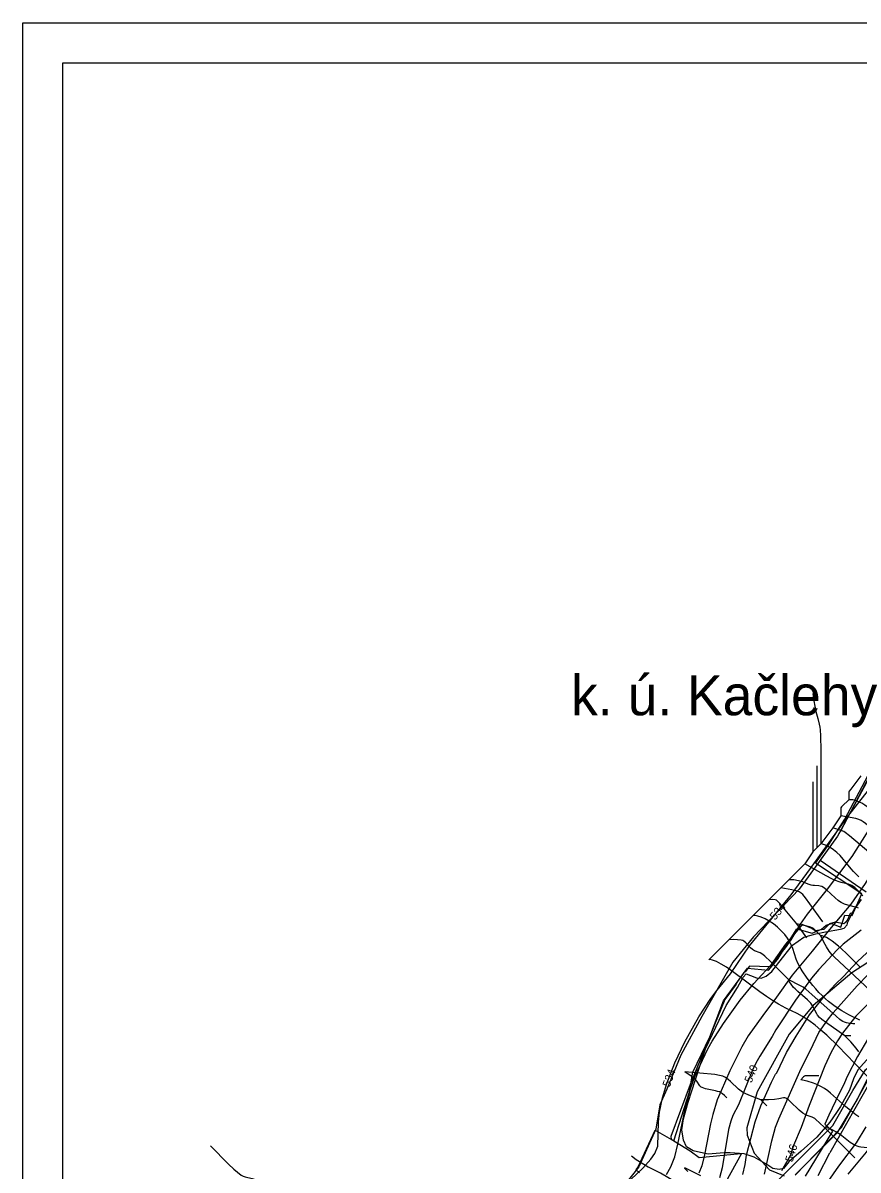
# Model space of a CAD drawing. Extents: x -709584 to -702006, y -1161789 to -1157496.
# Drawn here: x -709584 to -708540, y -1158930 to -1157496 of the extents above; entities that cross this region are included whole.
import ezdxf

# ---------------------------------------------------------------- set-up
doc = ezdxf.new("R2010")
doc.units = 0
for name, color, linetype in [('102_obvod PÚ', 7, 'Continuous'), ('103_hranice KÚ', 7, 'Continuous'), ('104_název KÚ', 7, 'Continuous'), ('110_silnice II. třídy a III. třídy', 7, 'Continuous'), ('120_vrstevnice hlavní', 7, 'Continuous'), ('121_vrstevnice hlavní_popis', 7, 'Continuous'), ('122_vrstevnice základní', 7, 'Continuous'), ('408_BPEJ_linie', 7, 'Continuous'), ('411_akumulovaný odtok', 7, 'Continuous'), ('419_LPIS PB', 7, 'Continuous'), ('501_vodní tok', 7, 'Continuous'), ('800_mřížka', 7, 'Continuous')]:
    doc.layers.add(name, color=color, linetype=linetype)

msp = doc.modelspace()

# ---------------------------------------------------------------- linework, layer by layer
at = {"layer": '102_obvod PÚ'}
for points in [[(-708813.3, -1158933.4), (-708817.7, -1158929.6), (-708815.4, -1158926.5), (-708793.7, -1158880.1), (-708770.5, -1158893.3), (-708750.8, -1158832), (-708746.8, -1158807.3), (-708725.5, -1158763.1), (-708708.5, -1158718.2), (-708678.4, -1158677.6), (-708652.2, -1158679.9), (-708641.1, -1158666.5), (-708617, -1158628.4), (-708597.6, -1158633.7), (-708586.1, -1158628.9), (-708580, -1158623.8), (-708573.6, -1158621.5), (-708561.7, -1158626.2), (-708556.8, -1158611.3), (-708547.7, -1158611.7), (-708535.6, -1158584.7), (-708593.5, -1158546.1), (-708576.9, -1158523.1), (-708562.5, -1158500.5), (-708557, -1158491.2), (-708524.4, -1158430.1)], [(-707921.8, -1158971), (-707999.1, -1158885.4), (-708014, -1158900), (-708117.7, -1158840.9), (-708144.9, -1158823.8), (-708143.2, -1158818), (-708120.7, -1158790.7), (-708182.3, -1158755), (-708195.8, -1158778.2), (-708236.7, -1158752.8), (-708244.6, -1158757.8), (-708255.9, -1158750.9), (-708298.9, -1158724), (-708301.6, -1158715.7), (-708309.8, -1158710.6), (-708354.7, -1158714.5), (-708370.1, -1158717.6), (-708390.1, -1158717.3), (-708405.6, -1158715.6), (-708506.3, -1158796.6), (-708529, -1158816.5), (-708541.9, -1158842.1), (-708567, -1158883.8), (-708618.5, -1158935.5)]]:
    msp.add_lwpolyline(points, dxfattribs=at)
at = {"layer": '103_hranice KÚ'}
msp.add_lwpolyline([(-708525.2, -1158435.6), (-708554.4, -1158491.4), (-708566, -1158512.4), (-708599.3, -1158558.9), (-708614.1, -1158578.7), (-708671.1, -1158638.5), (-708697, -1158669.9), (-708735.7, -1158737.7), (-708761.7, -1158786), (-708779.1, -1158828.5), (-708787.9, -1158848.4), (-708792.9, -1158878.8), (-708814.3, -1158925.7), (-708857.7, -1158980.1)], dxfattribs=at)
msp.add_lwpolyline([(-708525.2, -1158435.6), (-708554.4, -1158491.4), (-708566, -1158512.4), (-708599.3, -1158558.9), (-708614.1, -1158578.7), (-708671.1, -1158638.5), (-708697, -1158669.9), (-708735.7, -1158737.7), (-708761.7, -1158786), (-708779.1, -1158828.5), (-708787.9, -1158848.4), (-708792.9, -1158878.8), (-708814.3, -1158925.7), (-708857.7, -1158980.1)], dxfattribs=at)
at = {"layer": '110_silnice II. třídy a III. třídy'}
msp.add_lwpolyline([(-708704.4, -1159007.2), (-708617.3, -1158919.6), (-708571.8, -1158874.2), (-708546.8, -1158830.3), (-708531, -1158804.5), (-708476, -1158757.1), (-708390.8, -1158691.1), (-708373, -1158681.6), (-708289.6, -1158664.2), (-708263.7, -1158660.9), (-708218.7, -1158674.7), (-708130.2, -1158710.6), (-708061.3, -1158767.5), (-707984.1, -1158831.3), (-707891.2, -1158926), (-707846, -1158974.2)], dxfattribs=at)
at = {"layer": '120_vrstevnice hlavní'}
for points in [[(-708536.6, -1158629.9), (-708559.1, -1158647.7), (-708566.6, -1158654.4), (-708589.2, -1158679.1), (-708598.4, -1158690.1), (-708618.6, -1158717.3), (-708643.1, -1158754.7), (-708647.8, -1158763), (-708663.1, -1158787.4), (-708667.9, -1158796), (-708672.2, -1158805), (-708689.9, -1158848.4), (-708696.9, -1158861.7), (-708699.4, -1158868.7), (-708702.1, -1158879), (-708710.1, -1158927), (-708713.5, -1158939.6)], [(-708523.4, -1158816.8), (-708575.5, -1158908.3)], [(-708590.2, -1158936.7), (-708575.5, -1158908.3)]]:
    msp.add_lwpolyline(points, dxfattribs=at)
at = {"layer": '122_vrstevnice základní'}
for points in [[(-708422.3, -1158397.3), (-708431.3, -1158415.6), (-708438.3, -1158427), (-708472.2, -1158476), (-708487.1, -1158501.6), (-708497.5, -1158517.1), (-708531.5, -1158571.6), (-708549.4, -1158597.7), (-708575.8, -1158629.3), (-708597.5, -1158656.3), (-708622.8, -1158686.1), (-708642.1, -1158713.9), (-708659.5, -1158736.6), (-708677.8, -1158762.1), (-708685.6, -1158775.9), (-708700.4, -1158805.6), (-708711.6, -1158830.7), (-708716.2, -1158842.2), (-708721.9, -1158860.4), (-708724.8, -1158871.9), (-708732.2, -1158910.7), (-708735.5, -1158924.4), (-708739.1, -1158933.6)], [(-708839.8, -1158956), (-708809.1, -1158927.2), (-708799.5, -1158916.2), (-708794.4, -1158909), (-708790.5, -1158899.9), (-708789.9, -1158869.6), (-708788.5, -1158857.6), (-708784.6, -1158839.6), (-708779.1, -1158821.6), (-708769.4, -1158795.6), (-708756.6, -1158769.6), (-708739.4, -1158738.4), (-708724.2, -1158715.3), (-708716.5, -1158704.9), (-708699.9, -1158684.4), (-708676.1, -1158649.4), (-708623.8, -1158585.7), (-708599.6, -1158553.1), (-708553.1, -1158488.1), (-708527.4, -1158455)], [(-708779.9, -1158935.3), (-708774.2, -1158925.9), (-708769.4, -1158913.3), (-708765.5, -1158897.6), (-708756.2, -1158853.6), (-708749.6, -1158828.4), (-708744.4, -1158812.7), (-708728.1, -1158778.1), (-708722.6, -1158768.7), (-708708.4, -1158746.7), (-708687.6, -1158717.3), (-708670.6, -1158696.7), (-708645.2, -1158669.3), (-708630.9, -1158652.1), (-708623.8, -1158641.9), (-708612.2, -1158622.7), (-708603.4, -1158610.1), (-708578.4, -1158578.7), (-708547.5, -1158537.9), (-708521.8, -1158497)], [(-708360.3, -1158513.6), (-708362.8, -1158531.3), (-708368.9, -1158565.6), (-708375.9, -1158586.1), (-708383.2, -1158601.6), (-708392.8, -1158617.7), (-708409.2, -1158639.6), (-708419.6, -1158651.6), (-708434.6, -1158666.6), (-708466.5, -1158693.7), (-708487.1, -1158714.1), (-708508.6, -1158738.9), (-708517.3, -1158750.1), (-708527.2, -1158764.4), (-708541.1, -1158788), (-708554.1, -1158812.7), (-708557.4, -1158820.7), (-708568.5, -1158843.5), (-708576.8, -1158861), (-708581.9, -1158872.4), (-708572.4, -1158881.1)], [(-708684.2, -1158935.3), (-708681.5, -1158923), (-708679.6, -1158911), (-708669.1, -1158869.3), (-708661.9, -1158849.6), (-708648.5, -1158819.9), (-708643.4, -1158810.1), (-708641.8, -1158808.1), (-708629.6, -1158783), (-708617.8, -1158762.4), (-708600.8, -1158735.7), (-708582.5, -1158713.1), (-708568.8, -1158697.9), (-708558.5, -1158688.1), (-708540.8, -1158669.1), (-708523.4, -1158652.9), (-708497.6, -1158627.6)], [(-708657.4, -1158935), (-708648.2, -1158893.3), (-708643.4, -1158876.2), (-708639.5, -1158865.9), (-708611.6, -1158802.9), (-708599.8, -1158780.1), (-708589.2, -1158758), (-708578.6, -1158742.6), (-708571.5, -1158733.3), (-708541.5, -1158699.7), (-708513.8, -1158671.3)], [(-708552.8, -1158935), (-708529.9, -1158907.3), (-708524.1, -1158899.3), (-708510.1, -1158877.3), (-708502.9, -1158863.3), (-708485.2, -1158824.7), (-708474.8, -1158807.6), (-708465.9, -1158795.6), (-708456.9, -1158785.3), (-708446.5, -1158774.7), (-708425.9, -1158756.7), (-708406.3, -1158741.7), (-708385.6, -1158724.4), (-708374.5, -1158714.1), (-708320.7, -1158676.7)], [(-708526.8, -1158721.3), (-708543.2, -1158737.4), (-708559.8, -1158758.6), (-708566.1, -1158768.4), (-708574.2, -1158783.1), (-708581.9, -1158799.6), (-708601.6, -1158849.3), (-708611.6, -1158876.7), (-708620.9, -1158899), (-708624.8, -1158911), (-708635.9, -1158930.7)], [(-708530.6, -1158875.6), (-708542.8, -1158895.6), (-708564.9, -1158924.9), (-708578.2, -1158943.9)], [(-708572.4, -1158881.1), (-708606.5, -1158937.6)]]:
    msp.add_lwpolyline(points, dxfattribs=at)
at = {"layer": '408_BPEJ_linie'}
for points in [[(-708524, -1158434.5), (-708554.1, -1158490.7), (-708554.4, -1158491.4), (-708554.8, -1158492), (-708562, -1158505.5), (-708562.8, -1158506.6), (-708566, -1158512.4), (-708587.7, -1158542.7), (-708530, -1158582)], [(-708536.5, -1158591.7), (-708545.1, -1158604.3), (-708548.1, -1158608.8), (-708550, -1158609), (-708553.1, -1158616.1), (-708556.1, -1158620.3), (-708558.2, -1158622.1), (-708569, -1158620), (-708576, -1158622), (-708583, -1158629), (-708594, -1158631), (-708598, -1158628), (-708610, -1158623), (-708617.5, -1158632), (-708631, -1158647.5), (-708651, -1158676), (-708676, -1158675), (-708681.2, -1158682), (-708683.2, -1158683.1), (-708691.7, -1158695.6), (-708692.7, -1158697.4), (-708707, -1158716.5), (-708750, -1158823), (-708774.5, -1158888), (-708774, -1158891), (-708750, -1158905.9), (-708739, -1158914), (-708686.7, -1158909.1), (-708686.1, -1158909.1), (-708712.5, -1158957.5)], [(-708501, -1158653), (-708548, -1158683.5), (-708596.5, -1158724), (-708626.5, -1158760), (-708666.5, -1158832), (-708679.5, -1158877), (-708679, -1158886), (-708670, -1158908.5), (-708651, -1158929.5), (-708632.5, -1158937)], [(-708619, -1158936), (-708593, -1158909.5), (-708561, -1158876.5), (-708526, -1158813.5)]]:
    msp.add_lwpolyline(points, dxfattribs=at)
at = {"layer": '411_akumulovaný odtok'}
for p, q in [((-708592, -1158424.5), (-708592, -1158527)), ((-708597, -1158444.5), (-708597, -1158532)), ((-708562, -1158487), (-708572, -1158502)), ((-708572, -1158502), (-708587, -1158522)), ((-708597, -1158532), (-708607, -1158547)), ((-708592, -1158527), (-708597, -1158532)), ((-708587, -1158522), (-708592, -1158527)), ((-708607, -1158547), (-708627, -1158567)), ((-708637, -1158577), (-708652, -1158592)), ((-708627, -1158567), (-708637, -1158577)), ((-708652, -1158592), (-708672, -1158612)), ((-708672, -1158612), (-708702, -1158642)), ((-708604.5, -1158639.5), (-708617, -1158622)), ((-708702, -1158642), (-708727, -1158667)), ((-708549.5, -1158762), (-708557, -1158762)), ((-708654.5, -1158849.5), (-708662, -1158842)), ((-708544.5, -1158914.5), (-708582, -1158877)), ((-708737, -1158937), (-708757, -1158927))]:
    msp.add_line(p, q, dxfattribs=at)
for points in [[(-708597, -1158334.5), (-708595.5, -1158343.5), (-708592.9, -1158356.8), (-708590.7, -1158365.7), (-708588.8, -1158372.7), (-708588.1, -1158376.2), (-708587.7, -1158379.8), (-708587.1, -1158387.1), (-708586.9, -1158405.7), (-708587, -1158522)], [(-708537, -1158437), (-708549.5, -1158453.7), (-708551.3, -1158456.5), (-708551.8, -1158457.7), (-708552, -1158459.7), (-708552, -1158467)], [(-708552, -1158467), (-708560, -1158475), (-708561, -1158476), (-708561.7, -1158477.1), (-708562, -1158479.4), (-708562, -1158487)], [(-708469.5, -1158514.5), (-708471.2, -1158512.8), (-708474, -1158510.8), (-708475.8, -1158509.9), (-708478, -1158509), (-708482.8, -1158507.8), (-708492.8, -1158506.7), (-708494.7, -1158506.2), (-708496.4, -1158505.6), (-708498.1, -1158504.8), (-708501.2, -1158502.5), (-708504.2, -1158499.9), (-708524.2, -1158479.9), (-708527.2, -1158477.3), (-708532, -1158473.7), (-708535.5, -1158471.4), (-708537.6, -1158470.3), (-708542.3, -1158468.4), (-708544.7, -1158467.7), (-708547, -1158467.3), (-708550.5, -1158467), (-708552, -1158467)], [(-708507, -1158517), (-708531.1, -1158496.8), (-708534.1, -1158494.5), (-708536.2, -1158493.1), (-708539.5, -1158491.6), (-708543.2, -1158490.7), (-708562, -1158487)], [(-708524.5, -1158534.5), (-708550.8, -1158512.2), (-708556.2, -1158508), (-708558.2, -1158506.8), (-708561.3, -1158505.5), (-708572, -1158502)], [(-708539.2, -1158563.3), (-708545.9, -1158556.7), (-708549, -1158553.3), (-708558.9, -1158541.4), (-708562.8, -1158536.9), (-708566.9, -1158533), (-708571.1, -1158529.5), (-708575.3, -1158526.7), (-708579.7, -1158524.4), (-708583.3, -1158522.8), (-708585.9, -1158522.1), (-708587, -1158522)], [(-708534.5, -1158587), (-708541, -1158580.2), (-708544.4, -1158576.9), (-708546.2, -1158575.5), (-708548.1, -1158574.3), (-708550.2, -1158573.4), (-708552.4, -1158572.7), (-708561.5, -1158570.5), (-708563.9, -1158569.8), (-708568.6, -1158567.9), (-708573.1, -1158565.7), (-708580, -1158562.1), (-708607, -1158547)], [(-708584.5, -1158619.5), (-708606.1, -1158589.8), (-708609.5, -1158585.5), (-708611.5, -1158583.6), (-708613.7, -1158582.2), (-708617.5, -1158580.8), (-708623, -1158579.6), (-708637, -1158577)], [(-708539.7, -1158602.6), (-708541.9, -1158601.8), (-708552.9, -1158598.7), (-708557.2, -1158597.4), (-708561.3, -1158595.5), (-708563.3, -1158594.3), (-708565.3, -1158592.8), (-708569.1, -1158589.6), (-708579.9, -1158579.5), (-708583.6, -1158576.7), (-708585.5, -1158575.6), (-708587.5, -1158574.9), (-708589.3, -1158574.5), (-708594.9, -1158574.4), (-708596.8, -1158574.2), (-708598.7, -1158573.8), (-708602.5, -1158572.5), (-708609.3, -1158569.8), (-708614.8, -1158568.2), (-708620.7, -1158567.2), (-708625.2, -1158567), (-708627, -1158567)], [(-708617, -1158622), (-708637.6, -1158597.2), (-708640.8, -1158593.7), (-708642.3, -1158592.7), (-708644.1, -1158592.2), (-708647.6, -1158591.9), (-708652, -1158592)], [(-708538.2, -1158742.6), (-708551.7, -1158735.8), (-708560.5, -1158730.8), (-708569, -1158725.2), (-708577.2, -1158719.1), (-708581, -1158715.8), (-708585.2, -1158711.8), (-708589.2, -1158707.7), (-708593, -1158703.4), (-708596.7, -1158699), (-708603.8, -1158689.9), (-708610.3, -1158680.7), (-708613.1, -1158676), (-708615.7, -1158671.2), (-708617.8, -1158666.4), (-708622, -1158653), (-708623.8, -1158648.5), (-708626, -1158644.2), (-708628.6, -1158639.9), (-708632, -1158635.4), (-708636.2, -1158630.9), (-708640.9, -1158626.4), (-708646, -1158622.3), (-708651.2, -1158618.8), (-708656.4, -1158615.8), (-708661.3, -1158613.7), (-708665.5, -1158612.5), (-708668.8, -1158611.9), (-708671.1, -1158611.8), (-708672, -1158612)], [(-708587, -1158637), (-708594.6, -1158629.3), (-708596.1, -1158628), (-708597.8, -1158627), (-708601, -1158626), (-708617, -1158622)], [(-708627, -1158692), (-708649.8, -1158669), (-708656.7, -1158662.5), (-708659.5, -1158660.3), (-708662.6, -1158658.4), (-708669.7, -1158655.8), (-708672.3, -1158654.2), (-708674.7, -1158652), (-708680.4, -1158645.7), (-708682.9, -1158643.7), (-708684.4, -1158643), (-708686.3, -1158642.5), (-708690.8, -1158642), (-708695.4, -1158641.8), (-708702, -1158642)], [(-708538.1, -1158675.9), (-708554.7, -1158659.1), (-708560.9, -1158653.2), (-708564.6, -1158650), (-708572.5, -1158643.9), (-708576.3, -1158641.3), (-708579.8, -1158639.2), (-708582.9, -1158637.8), (-708585, -1158637.1), (-708586.4, -1158636.9), (-708587, -1158637)], [(-708499.5, -1158729.5), (-708564.1, -1158669.1), (-708569.6, -1158663.9), (-708573.1, -1158660.3), (-708576.5, -1158656.2), (-708579.9, -1158650.8), (-708583, -1158645.2), (-708587, -1158637)], [(-708502.8, -1158839.9), (-708544.3, -1158796.5), (-708565.3, -1158775.1), (-708579.5, -1158761.4), (-708586.7, -1158754.9), (-708594.1, -1158748.6), (-708601.7, -1158742.9), (-708609.6, -1158737.8), (-708616.5, -1158734.1), (-708630.6, -1158727.4), (-708635.3, -1158724.9), (-708639.9, -1158722.3), (-708647.1, -1158717.9), (-708654.6, -1158712.9), (-708662.9, -1158706.9), (-708697.3, -1158681.5), (-708704.6, -1158676.4), (-708711.3, -1158672.3), (-708717.1, -1158669.2), (-708722.1, -1158667.3), (-708725.5, -1158666.6), (-708727, -1158667)], [(-708544.5, -1158747), (-708547, -1158747.1), (-708550.5, -1158746.8), (-708554.7, -1158745.9), (-708557.1, -1158745.1), (-708559.3, -1158744), (-708561.3, -1158742.7), (-708563, -1158741.5), (-708567.6, -1158737.5), (-708597.9, -1158710.2), (-708605.6, -1158703.6), (-708609, -1158701.3), (-708613, -1158699), (-708627, -1158692)], [(-708557, -1158762), (-708581, -1158745.1), (-708585.6, -1158741.5), (-708588.4, -1158739), (-708590.9, -1158736.2), (-708591.9, -1158734.6), (-708597.1, -1158724.4), (-708599.2, -1158721.2), (-708603.3, -1158717.1), (-708615.6, -1158706.8), (-708619.1, -1158703.5), (-708620.9, -1158701.5), (-708623.8, -1158697.7), (-708625.8, -1158694.4), (-708627, -1158692)], [(-708539.2, -1158782), (-708542.7, -1158777.6), (-708549.5, -1158769.7), (-708554.8, -1158764.1), (-708557, -1158762)], [(-708704.5, -1158839.5), (-708707.4, -1158836.6), (-708709.6, -1158834.6), (-708712.1, -1158832.9), (-708713.4, -1158832.2), (-708715.8, -1158831.4), (-708718.3, -1158830.8), (-708730.8, -1158828.3), (-708733.1, -1158827.6), (-708735.3, -1158826.7), (-708736.3, -1158826.1), (-708737.9, -1158824.5), (-708741.8, -1158818.5), (-708744.3, -1158815.8), (-708748.7, -1158812.4), (-708757, -1158807)], [(-708662, -1158842), (-708676.7, -1158836.2), (-708681.2, -1158834.2), (-708684.8, -1158832.3), (-708686.5, -1158831.2), (-708689.6, -1158828.8), (-708699.8, -1158819.1), (-708702.8, -1158816.5), (-708705.9, -1158814.2), (-708707.6, -1158813.3), (-708709.4, -1158812.5), (-708713.3, -1158811.5), (-708719.4, -1158810.5), (-708757, -1158807)], [(-708589.5, -1158812), (-708603.6, -1158812), (-708606.4, -1158812.2), (-708607.2, -1158812.5), (-708608.3, -1158813.3), (-708612, -1158817)], [(-708539.5, -1158863.1), (-708542.9, -1158860.7), (-708549.4, -1158855.6), (-708555.8, -1158850.2), (-708574.6, -1158833.6), (-708578.2, -1158830.8), (-708582.3, -1158827.9), (-708586.9, -1158825.2), (-708591.7, -1158822.8), (-708596, -1158821.1), (-708603.9, -1158818.7), (-708609.7, -1158817.4), (-708612, -1158817)], [(-708582, -1158877), (-708588.8, -1158870.2), (-708592.5, -1158866.9), (-708594.3, -1158865.5), (-708596, -1158864.4), (-708597.6, -1158863.5), (-708605, -1158861.2), (-708606.4, -1158860.5), (-708609.5, -1158858.6), (-708613.9, -1158854.9), (-708625, -1158843.9), (-708627.8, -1158841.6), (-708629.2, -1158840.7), (-708630.6, -1158840), (-708632, -1158839.6), (-708633.3, -1158839.6), (-708639.2, -1158840.9), (-708644.9, -1158841.5), (-708652.3, -1158841.9), (-708662, -1158842)], [(-708469.5, -1158939.5), (-708502.4, -1158913.2), (-708508.7, -1158908.6), (-708513.1, -1158905.9), (-708515.3, -1158904.7), (-708517.6, -1158903.8), (-708519.9, -1158903.2), (-708524.6, -1158902.4), (-708536.7, -1158901.2), (-708539, -1158900.7), (-708541.3, -1158900.1), (-708543.6, -1158899.2), (-708545.8, -1158898), (-708550, -1158895.3), (-708562.5, -1158885.5), (-708568, -1158881.9), (-708570.8, -1158880.3), (-708573.6, -1158878.9), (-708576.3, -1158877.9), (-708580.3, -1158877), (-708581.5, -1158876.9), (-708582, -1158877)], [(-709349.5, -1158899.5), (-709327.2, -1158922.2), (-709320.4, -1158928.7), (-709315.9, -1158932.6), (-709311.2, -1158936), (-709308.8, -1158937.4), (-709306.4, -1158938.4), (-709297.4, -1158940.3), (-709294.9, -1158941.3), (-709292.4, -1158942.7), (-709289.9, -1158944.2), (-709285, -1158947.9), (-709277.8, -1158953.9), (-709263.5, -1158966.8), (-709256.6, -1158973.4), (-709252.5, -1158978), (-709250.6, -1158980.9), (-709249.1, -1158984.3), (-709248, -1158988), (-709247.4, -1158991.8), (-709247, -1158995.6), (-709246.8, -1159002.3), (-709247, -1159007)], [(-708753.2, -1158931.5), (-708755.3, -1158929.3), (-708756.6, -1158927.7), (-708757, -1158927)]]:
    msp.add_lwpolyline(points, dxfattribs=at)
at = {"layer": '419_LPIS PB'}
msp.add_lwpolyline([(-708526.1, -1158788.3), (-708540.6, -1158804.6), (-708546, -1158815.7), (-708551.1, -1158829.8), (-708557.4, -1158841), (-708562.3, -1158850.5), (-708567.2, -1158857.9), (-708575.6, -1158870.1), (-708591.9, -1158888.8), (-708611.2, -1158906.1), (-708626.9, -1158919.3), (-708633.4, -1158927.8), (-708638.8, -1158929.2), (-708646.7, -1158927.9), (-708655.7, -1158921.8), (-708670.2, -1158913.8), (-708682.7, -1158909.3), (-708700.2, -1158908.3), (-708707.7, -1158908.3), (-708727.7, -1158909.8), (-708737.3, -1158907.8), (-708746.3, -1158905.8), (-708754.8, -1158900.8), (-708758.6, -1158892.5), (-708760.7, -1158879.4), (-708758.6, -1158865.6), (-708752.5, -1158845.1), (-708743.6, -1158816.7), (-708730.8, -1158778.5), (-708705.1, -1158724), (-708691, -1158701.5), (-708683.9, -1158688.7), (-708680.1, -1158684.6), (-708674.9, -1158686.5), (-708667.2, -1158689.7), (-708661.2, -1158690.1), (-708655.2, -1158687.6), (-708648.2, -1158681.6), (-708639.2, -1158670.5), (-708622.1, -1158648.9), (-708608.1, -1158638.9), (-708593.1, -1158634.4), (-708581.1, -1158631.9), (-708562.4, -1158628.9), (-708557.5, -1158627.4), (-708554, -1158623.3), (-708553.2, -1158620), (-708545.1, -1158604.3), (-708536.5, -1158591.7)], dxfattribs=at)
at = {"layer": '501_vodní tok'}
msp.add_lwpolyline([(-708185.8, -1159173.3), (-708217.1, -1159164.5), (-708233.3, -1159155.6), (-708277.3, -1159131.2), (-708335, -1159111.8), (-708393.2, -1159099.2), (-708443.1, -1159088.8), (-708478.4, -1159076), (-708511.6, -1159062.2), (-708570.1, -1159043.4), (-708670.5, -1158995.4), (-708750.7, -1158954.8), (-708757.7, -1158951.3), (-708787.2, -1158933.5), (-708802.4, -1158926.3), (-708802.6, -1158926.2), (-708817.7, -1158916.8), (-708823.3, -1158912.6)], dxfattribs=at)
at = {"layer": '800_mřížka'}
for points in [[(-702006.5, -1161765.5), (-709584.1, -1161765.5), (-709584.1, -1157496.5), (-702006.5, -1157496.5)], [(-702056.5, -1161715.5), (-709534.1, -1161715.5), (-709534.1, -1157546.5), (-702056.5, -1157546.5)]]:
    msp.add_lwpolyline(points, close=True, dxfattribs=at)

# ---------------------------------------------------------------- texts
at = {"layer": '104_název KÚ'}
msp.add_text('k. ú. Kačlehy', height=50, dxfattribs=at).set_placement((-708899, -1158361.5))
at = {"layer": '121_vrstevnice hlavní_popis'}
for s, rotation, p in [('534', 50.4721, (-708644, -1158618.2)), ('534', 69.8832, (-708775.8, -1158826.9)), ('540', 67.8419, (-708673.6, -1158821.6)), ('546', 73.2741, (-708622.2, -1158920.6))]:
    msp.add_text(s, height=10, rotation=rotation, dxfattribs=at).set_placement(p)

doc.saveas('drawing.dxf')
